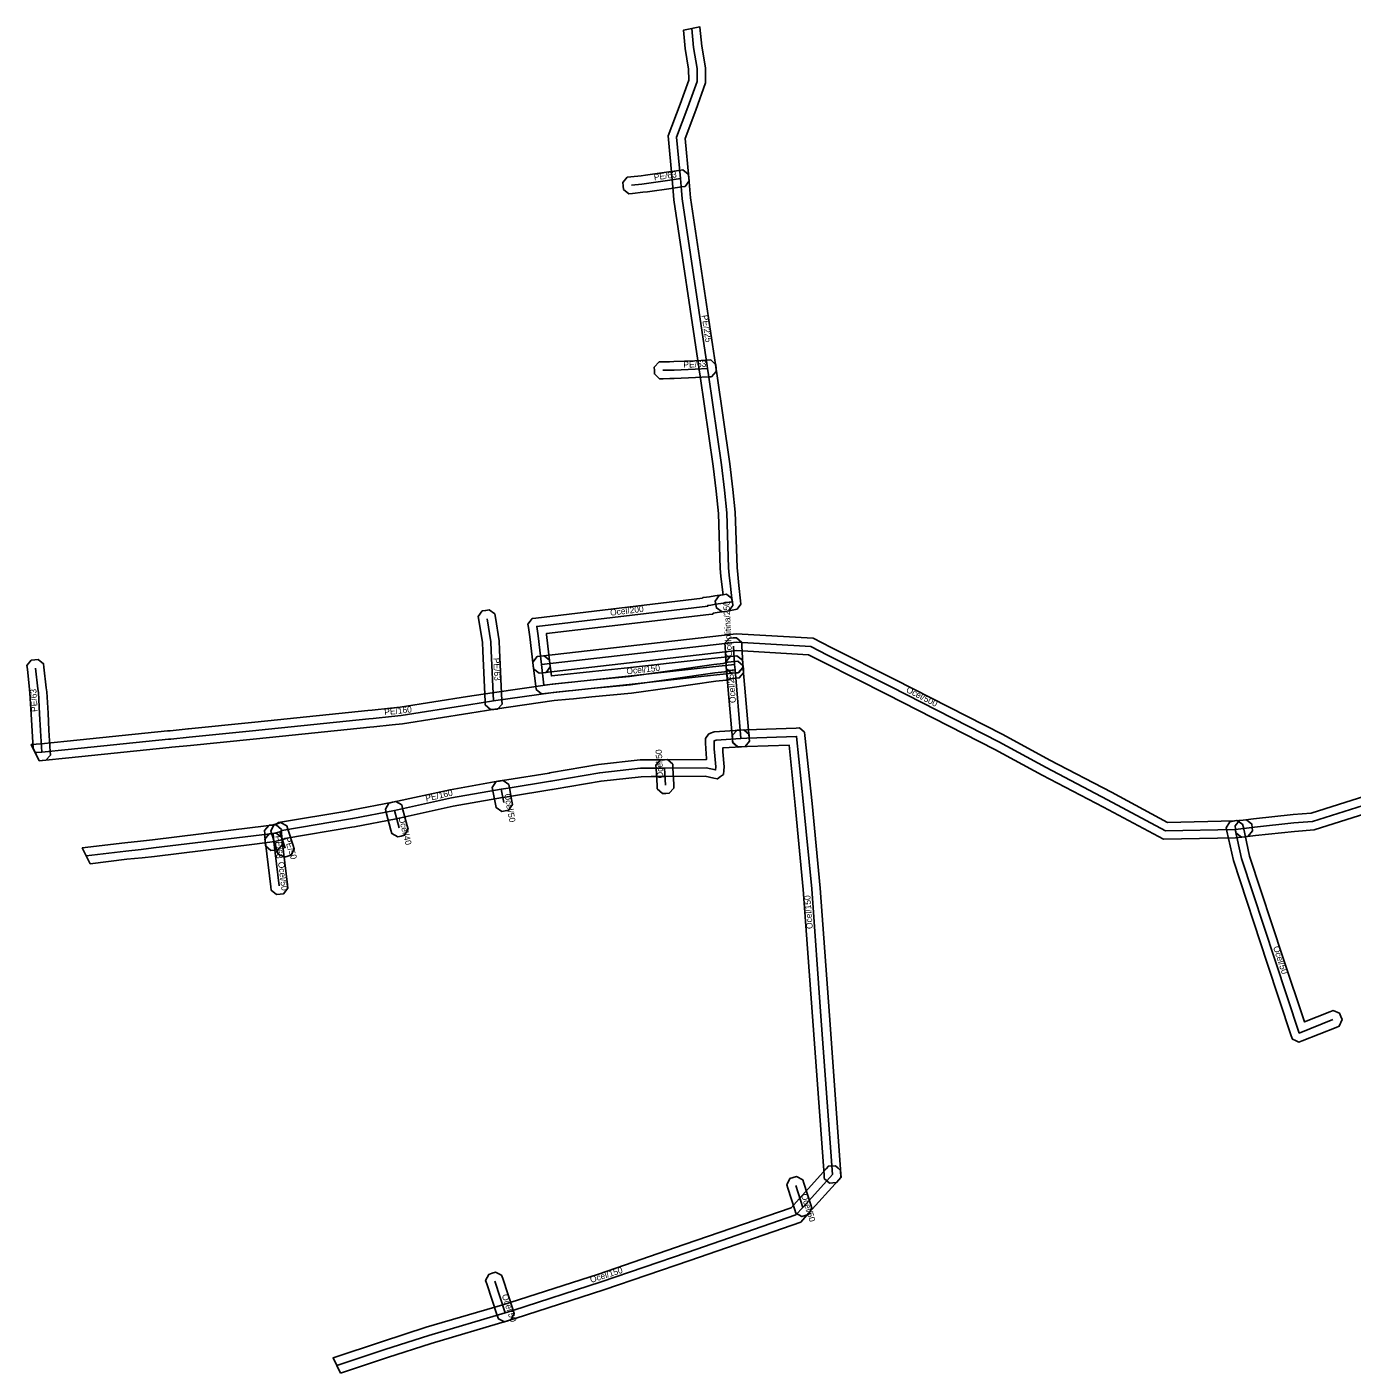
# Model space of a CAD drawing. Extents: x -760566 to -760255, y -976320 to -976047.
# Drawn here: x -760566 to -760408.2, y -976228 to -976067.7 of the extents above; entities that cross this region are included whole.
import ezdxf

# ---------------------------------------------------------------- set-up
doc = ezdxf.new("R2010")
doc.units = 0
for name, color, linetype in [('1', 7, 'Continuous'), ('14', 7, 'Continuous'), ('18', 7, 'Continuous'), ('20', 7, 'Continuous')]:
    doc.layers.add(name, color=color, linetype=linetype)

msp = doc.modelspace()

# ---------------------------------------------------------------- linework, layer by layer
at = {"layer": '1'}
for points in [[(-760487.58, -976070.24), (-760487.8, -976068.07), (-760485.83, -976067.68), (-760485.83, -976067.72), (-760485.6, -976069.98), (-760485.18, -976072.54), (-760485.16, -976074.34), (-760486.33, -976077.59), (-760487.6, -976080.95), (-760487.16, -976085.66), (-760487.04, -976087.07), (-760486.95, -976088.04), (-760483.98, -976107.89), (-760483.93, -976108.22), (-760483.82, -976108.98), (-760482.27, -976119.73), (-760481.93, -976122.76), (-760481.64, -976125.48), (-760481.42, -976132.05), (-760481.34, -976132.9), (-760481.2, -976134.2), (-760481, -976136.03), (-760480.95, -976136.42), (-760481.42, -976137.05), (-760481.8, -976137.12), (-760482, -976137.16), (-760482.19, -976137.2), (-760482.8, -976137.3), (-760483.2, -976137.36), (-760483.88, -976136.88), (-760483.95, -976136.47), (-760484.01, -976136.07), (-760483.53, -976135.39), (-760483.12, -976135.32), (-760483.09, -976135.32), (-760483.19, -976134.42), (-760483.33, -976133.1), (-760483.42, -976132.17), (-760483.64, -976125.62), (-760483.91, -976122.98), (-760484.25, -976119.99), (-760485.8, -976109.26), (-760485.91, -976108.52), (-760485.96, -976108.19), (-760488.93, -976088.28), (-760489.03, -976087.25), (-760489.16, -976085.84), (-760489.64, -976080.67), (-760488.21, -976076.89), (-760487.16, -976074), (-760487.18, -976072.72)], [(-760487.61, -976086.68), (-760488.02, -976086.74), (-760489.28, -976086.92), (-760492.08, -976087.32), (-760492.63, -976087.38), (-760493.88, -976087.52), (-760494.29, -976087.56), (-760494.93, -976087.04), (-760494.97, -976086.62), (-760495.02, -976086.21), (-760494.5, -976085.57), (-760494.08, -976085.53), (-760492.85, -976085.4), (-760492.34, -976085.34), (-760489.56, -976084.94), (-760488.3, -976084.76), (-760487.89, -976084.7), (-760487.23, -976085.2), (-760487.17, -976085.61), (-760487.11, -976086.02)], [(-760484.46, -976109.35), (-760484.87, -976109.37), (-760486.38, -976109.44), (-760488.89, -976109.55), (-760489.43, -976109.56), (-760490.23, -976109.58), (-760490.65, -976109.59), (-760491.25, -976109.02), (-760491.26, -976108.6), (-760491.27, -976108.19), (-760490.7, -976107.59), (-760490.29, -976107.58), (-760489.47, -976107.56), (-760488.95, -976107.55), (-760486.46, -976107.44), (-760484.97, -976107.37), (-760484.55, -976107.35), (-760483.94, -976107.91), (-760483.92, -976108.32), (-760483.9, -976108.74)], [(-760505.39, -976138.09), (-760485.54, -976135.74), (-760485.49, -976135.66), (-760485.04, -976135.6), (-760484.68, -976135.55), (-760484.08, -976135.46), (-760483.2, -976135.33), (-760483.1, -976135.32), (-760482.69, -976135.26), (-760482.03, -976135.76), (-760481.97, -976136.17), (-760481.91, -976136.58), (-760482.41, -976137.24), (-760482.82, -976137.3), (-760482.92, -976137.31), (-760483.8, -976137.44), (-760484.25, -976137.51), (-760484.32, -976137.61), (-760484.77, -976137.66), (-760504.12, -976139.95), (-760504.11, -976140.06), (-760503.7, -976143.51), (-760503.66, -976143.92), (-760504.17, -976144.57), (-760504.58, -976144.62), (-760504.99, -976144.66), (-760505.64, -976144.15), (-760505.69, -976143.74), (-760506.09, -976140.32), (-760506.26, -976139.23), (-760506.32, -976138.81), (-760506.07, -976138.47), (-760505.81, -976138.14)], [(-760510.27, -976137.6), (-760510.2, -976138.01), (-760509.75, -976140.82), (-760509.7, -976141.93), (-760509.42, -976147.92), (-760509.4, -976148.34), (-760509.96, -976148.95), (-760510.37, -976148.97), (-760510.79, -976148.99), (-760511.4, -976148.43), (-760511.42, -976148.02), (-760511.7, -976142.03), (-760511.75, -976141.02), (-760512.18, -976138.33), (-760512.24, -976137.92), (-760511.76, -976137.25), (-760511.35, -976137.18), (-760510.94, -976137.12)], [(-760505.22, -976142.68), (-760504.81, -976142.63), (-760481.51, -976139.96), (-760472.35, -976140.49), (-760470.19, -976141.61), (-760462.62, -976145.4), (-760449.76, -976151.97), (-760444.15, -976155.03), (-760436.82, -976158.85), (-760430.16, -976162.43), (-760422.16, -976162.26), (-760421.16, -976162.15), (-760420.75, -976162.11), (-760420.1, -976162.63), (-760420.06, -976163.04), (-760420.01, -976163.45), (-760420.53, -976164.09), (-760420.94, -976164.14), (-760422.04, -976164.26), (-760430.64, -976164.44), (-760437.76, -976160.61), (-760445.09, -976156.79), (-760450.7, -976153.73), (-760463.52, -976147.18), (-760471.09, -976143.39), (-760472.89, -976142.47), (-760481.45, -976141.96), (-760504.58, -976144.62), (-760505, -976144.66), (-760505.64, -976144.15), (-760505.69, -976143.74), (-760505.74, -976143.33)], [(-760482.71, -976144.09), (-760482.73, -976143.68), (-760482.84, -976141.51), (-760482.86, -976141.1), (-760482.3, -976140.48), (-760481.89, -976140.46), (-760481.48, -976140.44), (-760480.86, -976141), (-760480.84, -976141.41), (-760480.73, -976143.57), (-760480.71, -976143.99), (-760481.27, -976144.6), (-760481.68, -976144.62), (-760482.09, -976144.65)], [(-760481.21, -976144.57), (-760481.62, -976144.62), (-760485.7, -976145.06), (-760493.9, -976145.95), (-760498.42, -976146.44), (-760502.9, -976146.92), (-760504.3, -976147.07), (-760504.71, -976147.12), (-760505.35, -976146.6), (-760505.4, -976146.2), (-760505.69, -976143.74), (-760505.74, -976143.33), (-760505.23, -976142.68), (-760504.81, -976142.63), (-760504.4, -976142.58), (-760503.75, -976143.09), (-760503.7, -976143.51), (-760503.53, -976144.98), (-760503.12, -976144.94), (-760498.63, -976144.45), (-760494.12, -976143.97), (-760485.91, -976143.08), (-760481.84, -976142.63), (-760481.43, -976142.59), (-760480.78, -976143.1), (-760480.74, -976143.52), (-760480.69, -976143.93)], [(-760481.92, -976152.94), (-760481.96, -976152.52), (-760482.66, -976144.37), (-760482.72, -976143.73), (-760482.77, -976143.32), (-760482.25, -976142.68), (-760481.84, -976142.63), (-760481.43, -976142.59), (-760480.78, -976143.1), (-760480.74, -976143.52), (-760480.67, -976144.17), (-760479.96, -976152.35), (-760479.93, -976152.77), (-760480.46, -976153.4), (-760480.88, -976153.43), (-760481.29, -976153.47)], [(-760564.16, -976155.06), (-760564.52, -976155.08), (-760565.25, -976153.59), (-760565.37, -976151.56), (-760565.48, -976149.56), (-760565.63, -976147.05), (-760565.67, -976146.62), (-760565.94, -976144.17), (-760565.99, -976143.76), (-760565.47, -976143.11), (-760565.06, -976143.07), (-760564.65, -976143.02), (-760564, -976143.54), (-760563.96, -976143.95), (-760563.69, -976146.4), (-760563.63, -976146.88), (-760563.48, -976149.44), (-760563.37, -976151.44), (-760563.22, -976154), (-760563.2, -976154.42), (-760563.75, -976155.03)], [(-760564.52, -976155.08), (-760565.47, -976153.15), (-760564.31, -976153.06), (-760561.18, -976152.74), (-760549.24, -976151.54), (-760548.94, -976151.51), (-760546.8, -976151.28), (-760546.8, -976151.28), (-760546.76, -976151.28), (-760539.23, -976150.52), (-760537.3, -976150.32), (-760525.37, -976149.09), (-760524.87, -976149.05), (-760522.68, -976148.82), (-760521.53, -976148.7), (-760513.53, -976147.44), (-760510.57, -976146.98), (-760503.44, -976145.95), (-760501.59, -976145.78), (-760501.09, -976145.72), (-760498.91, -976145.51), (-760494.24, -976145.04), (-760489.72, -976144.41), (-760484.18, -976143.62), (-760483.08, -976143.5), (-760482.53, -976143.34), (-760482.1, -976143.3), (-760481.74, -976143.27), (-760481.33, -976143.24), (-760480.7, -976143.77), (-760480.66, -976144.19), (-760480.63, -976144.6), (-760481.16, -976145.23), (-760481.58, -976145.27), (-760481.92, -976145.3), (-760482.15, -976145.32), (-760482.7, -976145.48), (-760483.94, -976145.6), (-760489.44, -976146.39), (-760494, -976147.02), (-760498.71, -976147.49), (-760500.89, -976147.71), (-760501.41, -976147.77), (-760503.2, -976147.93), (-760510.27, -976148.96), (-760513.23, -976149.42), (-760521.27, -976150.68), (-760522.48, -976150.81), (-760524.67, -976151.04), (-760525.17, -976151.08), (-760537.1, -976152.31), (-760539.03, -976152.51), (-760546.5, -976153.26), (-760546.5, -976153.26), (-760548.74, -976153.49), (-760549.04, -976153.53), (-760560.98, -976154.73), (-760564.13, -976155.06)], [(-760558.47, -976167.37), (-760559.41, -976165.47), (-760554.33, -976164.85), (-760552.48, -976164.67), (-760551.04, -976164.49), (-760539.12, -976163.03), (-760536.84, -976162.76), (-760536.27, -976162.61), (-760536.02, -976162.45), (-760527.65, -976161.04), (-760527.37, -976160.98), (-760522.42, -976160.03), (-760515.6, -976158.54), (-760510.35, -976157.61), (-760509.68, -976157.5), (-760508.82, -976157.36), (-760503.81, -976156.55), (-760503.73, -976156.53), (-760503.52, -976156.5), (-760497.9, -976155.53), (-760492.97, -976154.99), (-760491.66, -976154.98), (-760490.06, -976154.97), (-760485.04, -976154.94), (-760485.11, -976154.15), (-760485.13, -976153.74), (-760485.14, -976153.49), (-760485.16, -976153.17), (-760485.16, -976152.73), (-760485.16, -976152.43), (-760484.83, -976151.93), (-760484.56, -976151.82), (-760484.15, -976151.63), (-760481.02, -976151.44), (-760480.61, -976151.41), (-760479.99, -976151.96), (-760479.96, -976152.38), (-760479.94, -976152.79), (-760480.48, -976153.41), (-760480.9, -976153.44), (-760483.13, -976153.57), (-760483.13, -976153.64), (-760483.11, -976154.01), (-760482.95, -976155.82), (-760482.98, -976156.26), (-760483.02, -976156.71), (-760483.38, -976156.98), (-760483.75, -976157.25), (-760484.19, -976157.16), (-760485.21, -976156.94), (-760490.05, -976156.97), (-760491.64, -976156.98), (-760492.85, -976156.99), (-760497.62, -976157.51), (-760503.19, -976158.47), (-760503.41, -976158.51), (-760503.48, -976158.52), (-760508.5, -976159.34), (-760509.35, -976159.48), (-760510.01, -976159.59), (-760515.22, -976160.5), (-760522.02, -976161.99), (-760526.99, -976162.95), (-760527.29, -976163), (-760535.28, -976164.35), (-760535.47, -976164.47), (-760536.48, -976164.72), (-760538.88, -976165.02), (-760550.8, -976166.48), (-760552.26, -976166.65), (-760554.11, -976166.83)], [(-760471.03, -976204.84), (-760471.06, -976204.43), (-760472.42, -976185.57), (-760473.53, -976170.41), (-760474.48, -976160.4), (-760475.23, -976153.22), (-760480.2, -976153.41), (-760480.92, -976153.44), (-760481.34, -976153.45), (-760481.94, -976152.89), (-760481.96, -976152.47), (-760481.97, -976152.06), (-760481.41, -976151.45), (-760481, -976151.44), (-760480.28, -976151.41), (-760474.37, -976151.19), (-760473.97, -976151.18), (-760473.38, -976151.69), (-760473.33, -976152.09), (-760472.49, -976160.2), (-760471.53, -976170.25), (-760470.42, -976185.43), (-760469.06, -976204.29), (-760469.03, -976204.7), (-760469.58, -976205.33), (-760469.99, -976205.36), (-760470.4, -976205.39)], [(-760490.93, -976158.44), (-760490.95, -976158.03), (-760491.06, -976156.03), (-760491.08, -976155.61), (-760490.52, -976154.99), (-760490.11, -976154.97), (-760489.7, -976154.95), (-760489.08, -976155.51), (-760489.06, -976155.92), (-760488.95, -976157.93), (-760488.93, -976158.34), (-760489.49, -976158.96), (-760489.9, -976158.98), (-760490.31, -976159)], [(-760508.61, -976157.9), (-760508.53, -976158.31), (-760508.23, -976159.89), (-760508.15, -976160.3), (-760508.62, -976160.98), (-760509.03, -976161.06), (-760509.44, -976161.14), (-760510.12, -976160.67), (-760510.2, -976160.26), (-760510.5, -976158.68), (-760510.57, -976158.27), (-760510.1, -976157.58), (-760509.7, -976157.51), (-760509.29, -976157.43)], [(-760521.36, -976160.35), (-760521.25, -976160.76), (-760520.7, -976162.85), (-760520.6, -976163.25), (-760521.02, -976163.96), (-760521.42, -976164.07), (-760521.82, -976164.17), (-760522.53, -976163.76), (-760522.64, -976163.35), (-760523.19, -976161.26), (-760523.29, -976160.86), (-760522.88, -976160.15), (-760522.47, -976160.04), (-760522.07, -976159.94)], [(-760535.69, -976163.27), (-760535.66, -976163.68), (-760535.6, -976164.68), (-760535.58, -976165.09), (-760536.12, -976165.71), (-760536.54, -976165.74), (-760536.95, -976165.77), (-760537.57, -976165.22), (-760537.6, -976164.8), (-760537.66, -976163.8), (-760537.68, -976163.39), (-760537.13, -976162.77), (-760536.72, -976162.74), (-760536.31, -976162.72)], [(-760535.05, -976162.84), (-760534.92, -976163.23), (-760534.28, -976165.2), (-760534.15, -976165.59), (-760534.53, -976166.33), (-760534.92, -976166.46), (-760535.32, -976166.59), (-760536.05, -976166.21), (-760536.18, -976165.82), (-760536.82, -976163.85), (-760536.95, -976163.46), (-760536.57, -976162.72), (-760536.18, -976162.59), (-760535.79, -976162.46)], [(-760421.21, -976162.64), (-760421.12, -976163.05), (-760420.37, -976166.46), (-760416.38, -976178.59), (-760413.85, -976186.2), (-760410.82, -976184.99), (-760410.44, -976184.84), (-760409.68, -976185.16), (-760409.52, -976185.55), (-760409.37, -976185.93), (-760409.69, -976186.7), (-760410.08, -976186.85), (-760414.1, -976188.46), (-760414.5, -976188.62), (-760414.89, -976188.43), (-760415.28, -976188.25), (-760415.42, -976187.84), (-760418.28, -976179.21), (-760422.31, -976166.98), (-760423.08, -976163.47), (-760423.17, -976163.07), (-760422.72, -976162.37), (-760422.32, -976162.28), (-760421.91, -976162.19)], [(-760535.66, -976164.21), (-760535.61, -976164.62), (-760534.97, -976169.87), (-760534.92, -976170.28), (-760535.43, -976170.93), (-760535.84, -976170.98), (-760536.25, -976171.03), (-760536.9, -976170.52), (-760536.95, -976170.11), (-760537.59, -976164.86), (-760537.64, -976164.45), (-760537.13, -976163.8), (-760536.72, -976163.75), (-760536.31, -976163.7)], [(-760528.63, -976228.03), (-760529.52, -976226.22), (-760523.66, -976224.27), (-760518.44, -976222.58), (-760509.31, -976219.89), (-760508.43, -976219.62), (-760497.92, -976216.23), (-760487.7, -976212.71), (-760474.97, -976208.33), (-760474.34, -976207.63), (-760470.8, -976203.69), (-760470.53, -976203.38), (-760469.7, -976203.34), (-760469.39, -976203.62), (-760469.08, -976203.89), (-760469.04, -976204.72), (-760469.32, -976205.03), (-760472.85, -976208.96), (-760473.83, -976210.05), (-760487.04, -976214.61), (-760497.28, -976218.13), (-760507.83, -976221.54), (-760508.74, -976221.8), (-760517.84, -976224.49), (-760523.04, -976226.17)], [(-760473.59, -976205), (-760473.47, -976205.4), (-760472.64, -976207.99), (-760472.52, -976208.39), (-760472.9, -976209.12), (-760473.29, -976209.25), (-760473.69, -976209.38), (-760474.42, -976208.99), (-760474.55, -976208.6), (-760475.38, -976206), (-760475.5, -976205.61), (-760475.12, -976204.87), (-760474.72, -976204.75), (-760474.33, -976204.62)], [(-760509.46, -976216.37), (-760509.33, -976216.77), (-760508.08, -976220.53), (-760507.95, -976220.92), (-760508.32, -976221.66), (-760508.71, -976221.79), (-760509.1, -976221.93), (-760509.84, -976221.56), (-760509.97, -976221.16), (-760511.23, -976217.4), (-760511.36, -976217.01), (-760510.99, -976216.27), (-760510.6, -976216.14), (-760510.2, -976216)]]:
    msp.add_lwpolyline(points, close=True, dxfattribs=at)
msp.add_lwpolyline([(-760403.52, -976160.43), (-760412.68, -976163.31), (-760415.02, -976163.5), (-760419.69, -976164), (-760420.94, -976164.14), (-760421.35, -976164.19), (-760422, -976163.67), (-760422.05, -976163.25), (-760422.09, -976162.84), (-760421.57, -976162.2), (-760421.16, -976162.15), (-760419.91, -976162.02), (-760415.2, -976161.5), (-760413.06, -976161.33), (-760404.14, -976158.53)], dxfattribs=at)
at = {"layer": '14'}
for points in [[(-760482.96, -976136.31), (-760482.36, -976136.21), (-760482.18, -976136.18), (-760481.99, -976136.14), (-760482.19, -976134.31), (-760482.34, -976133), (-760482.42, -976132.11), (-760482.64, -976125.55), (-760482.92, -976122.87), (-760483.26, -976119.86), (-760484.81, -976109.12), (-760484.92, -976108.37), (-760484.97, -976108.04), (-760487.94, -976088.16), (-760488.03, -976087.16), (-760488.16, -976085.75), (-760488.62, -976080.81), (-760487.27, -976077.24), (-760486.16, -976074.17), (-760486.18, -976072.63), (-760486.59, -976070.11), (-760486.82, -976067.87)], [(-760488.16, -976085.75), (-760489.42, -976085.93), (-760492.21, -976086.33), (-760492.74, -976086.39), (-760493.98, -976086.52)], [(-760484.92, -976108.37), (-760486.42, -976108.44), (-760488.92, -976108.55), (-760489.45, -976108.56), (-760490.26, -976108.58)], [(-760511.19, -976138.17), (-760510.75, -976140.91), (-760510.75, -976140.91), (-760510.75, -976140.92), (-760510.7, -976141.98), (-760510.42, -976147.97)], [(-760504.7, -976143.62), (-760481.48, -976140.96), (-760472.62, -976141.48), (-760470.64, -976142.5), (-760463.07, -976146.29), (-760450.23, -976152.85), (-760444.62, -976155.91), (-760437.29, -976159.73), (-760430.4, -976163.43), (-760422.1, -976163.26), (-760421.05, -976163.15)], [(-760481.73, -976143.62), (-760481.84, -976141.46)], [(-760564.99, -976154.12), (-760564.22, -976154.06), (-760561.08, -976153.74), (-760549.14, -976152.53), (-760548.84, -976152.5), (-760546.66, -976152.27), (-760546.65, -976152.27), (-760539.13, -976151.51), (-760537.2, -976151.31), (-760525.27, -976150.09), (-760524.77, -976150.04), (-760522.58, -976149.81), (-760521.4, -976149.69), (-760513.38, -976148.43), (-760510.42, -976147.97), (-760503.32, -976146.94), (-760501.5, -976146.77), (-760500.99, -976146.72), (-760498.81, -976146.5), (-760494.12, -976146.03), (-760489.58, -976145.4), (-760484.06, -976144.61), (-760482.89, -976144.49), (-760482.34, -976144.33), (-760482.01, -976144.3), (-760481.66, -976144.27)], [(-760564.22, -976154.06), (-760564.37, -976151.53), (-760564.37, -976151.5), (-760564.48, -976149.5), (-760564.63, -976146.96), (-760564.68, -976146.51), (-760564.95, -976144.06)], [(-760481.73, -976143.62), (-760485.8, -976144.07), (-760494.01, -976144.96), (-760498.52, -976145.45), (-760503.01, -976145.93), (-760504.41, -976146.08), (-760504.7, -976143.62)], [(-760480.96, -976152.44), (-760481.66, -976144.27), (-760481.73, -976143.62)], [(-760470.06, -976204.36), (-760471.42, -976185.5), (-760472.53, -976170.33), (-760473.49, -976160.3), (-760474.33, -976152.19), (-760480.24, -976152.41), (-760480.96, -976152.44)], [(-760480.96, -976152.44), (-760483.91, -976152.62), (-760484.16, -976152.73), (-760484.16, -976153.14), (-760484.14, -976153.44), (-760484.13, -976153.69), (-760484.11, -976154.07), (-760484.11, -976154.08), (-760483.95, -976155.82), (-760483.98, -976156.18), (-760485.11, -976155.94), (-760490.06, -976155.97), (-760491.65, -976155.98), (-760492.91, -976155.99), (-760497.76, -976156.52), (-760503.36, -976157.49), (-760503.57, -976157.52), (-760503.64, -976157.53), (-760508.66, -976158.35), (-760509.51, -976158.49), (-760510.18, -976158.6), (-760515.41, -976159.52), (-760522.22, -976161.01), (-760527.18, -976161.96), (-760527.47, -976162.02), (-760535.65, -976163.4), (-760535.65, -976163.4), (-760535.87, -976163.54), (-760536.66, -976163.74), (-760539, -976164.03), (-760550.92, -976165.48), (-760552.37, -976165.66), (-760554.22, -976165.84), (-760554.23, -976165.84), (-760558.94, -976166.42)], [(-760489.95, -976157.98), (-760490.06, -976155.97)], [(-760509.51, -976158.49), (-760509.21, -976160.08)], [(-760421.05, -976163.15), (-760419.8, -976163.01), (-760415.11, -976162.5), (-760412.87, -976162.32), (-760403.83, -976159.48), (-760400.36, -976158.28), (-760390.39, -976158.51), (-760382.83, -976159.31), (-760371.77, -976160.38), (-760363.65, -976160.91), (-760350.62, -976162.03), (-760341.46, -976163.08), (-760326.97, -976161.94), (-760313.93, -976160.93), (-760299.19, -976159.6)], [(-760522.22, -976161.01), (-760521.67, -976163.1)], [(-760535.87, -976163.54), (-760535.23, -976165.51)], [(-760422.1, -976163.26), (-760421.34, -976166.72), (-760417.33, -976178.9), (-760414.47, -976187.53), (-760410.45, -976185.92)], [(-760536.66, -976163.74), (-760536.6, -976164.74)], [(-760470.06, -976204.36), (-760473.6, -976208.3), (-760474.4, -976209.19), (-760487.37, -976213.66), (-760497.6, -976217.18), (-760508.13, -976220.58), (-760509.03, -976220.84), (-760518.14, -976223.54), (-760523.35, -976225.22), (-760529.08, -976227.12)]]:
    msp.add_lwpolyline(points, dxfattribs=at)
at = {"layer": '18'}
for points in [[(-760504.7, -976143.62), (-760505.1, -976140.19), (-760505.27, -976139.08), (-760484.89, -976136.67), (-760484.91, -976136.59), (-760484.54, -976136.54), (-760483.94, -976136.45), (-760483.06, -976136.32), (-760482.96, -976136.31)], [(-760536.6, -976164.74), (-760535.96, -976169.99)], [(-760474.42, -976205.7), (-760473.6, -976208.3)], [(-760510.28, -976217.08), (-760509.03, -976220.84)]]:
    msp.add_lwpolyline(points, dxfattribs=at)

# ---------------------------------------------------------------- texts
at = {"layer": '20'}
for s, rotation, p in [('PE/63', 8.1589, (-760491.27, -976085.97)), ('PE/225', 278.4993, (-760485.64, -976102.04)), ('PE/63', 2.5194, (-760487.79, -976108.29)), ('Ocelolitina/250', 92.9086, (-760481.99, -976142.69)), ('Ocel/200', 6.7441, (-760496.49, -976137.82)), ('PE/63', 272.6763, (-760510.45, -976142.85)), ('Ocel/150', 6.1491, (-760494.55, -976144.8)), ('Ocel/250', 94.8989, (-760481.54, -976148.18)), ('PE/63', 93.3572, (-760564.71, -976149.25)), ('Ocel/500', 332.9374, (-760461.35, -976146.87)), ('PE/160', 5.9722, (-760523.39, -976149.67)), ('Ocel/50', 93.0248, (-760490.2, -976157.17)), ('PE/160', 12.3416, (-760518.44, -976159.94)), ('Ocel/50', 280.6567, (-760509.16, -976159.08)), ('Ocel/40', 284.7436, (-760521.75, -976161.86)), ('PE/63', 273.4838, (-760536.43, -976164.04)), ('PE/50', 287.9976, (-760535.35, -976164.33)), ('Ocel/50', 276.9409, (-760536.08, -976167.17)), ('Ocel/150', 94.1849, (-760472.4, -976175.1)), ('Ocel/50', 288.223, (-760417.59, -976177.3)), ('Ocel/50', 287.6237, (-760473.81, -976206.8)), ('Ocel/150', 17.8946, (-760498.79, -976217.3)), ('Ocel/50', 288.4532, (-760509.45, -976218.76))]:
    msp.add_text(s, height=0.75, rotation=rotation, dxfattribs=at).set_placement(p)

doc.saveas('drawing.dxf')
